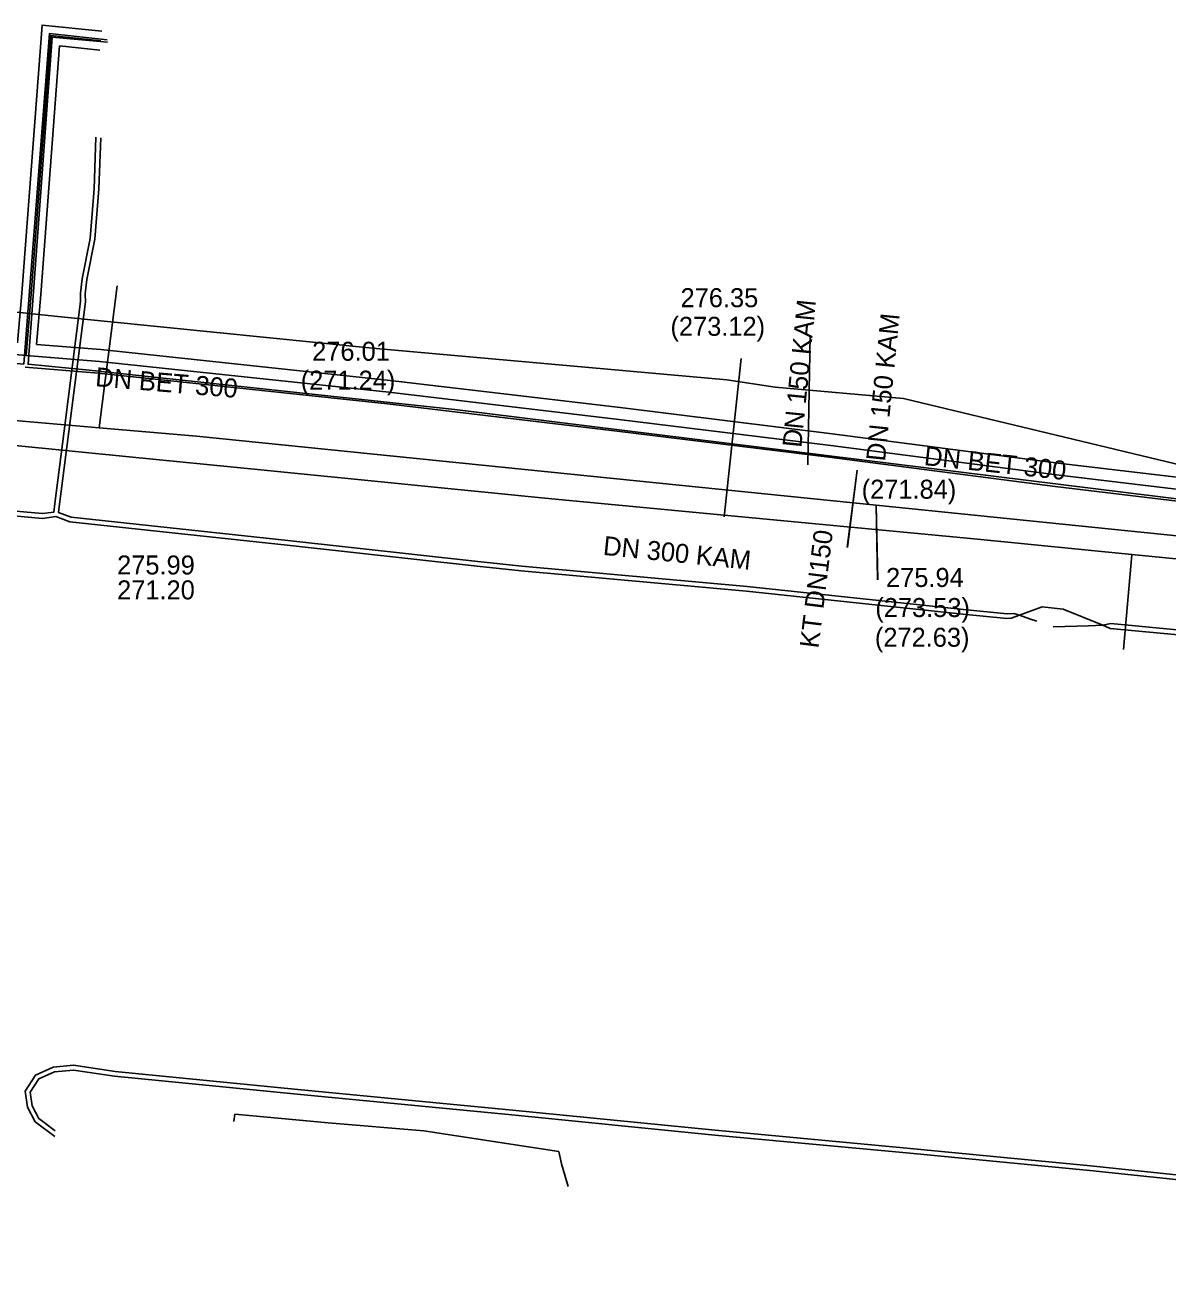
# Model space of a CAD drawing. Extents: x -598233 to -596890, y -1157848 to -1156431.
# Drawn here: x -597803.5 to -597755.4, y -1156911.9 to -1156859.1 of the extents above; entities that cross this region are included whole.
import ezdxf

# ---------------------------------------------------------------- set-up
doc = ezdxf.new("R2010")
doc.units = 0
for name, color, linetype in [('G_TEXTY', 7, 'Continuous'), ('G_ZNACKY', 7, 'Continuous'), ('Vrstva 1', 7, 'Continuous'), ('Vrstva 13', 7, 'Continuous'), ('Vrstva 25', 7, 'Continuous'), ('Vrstva 26', 7, 'Continuous'), ('Vrstva 4', 7, 'Continuous'), ('Vrstva 42', 7, 'Continuous'), ('Vrstva 5', 7, 'Continuous'), ('Vrstva 55', 7, 'Continuous'), ('Vrstva 8', 7, 'Continuous')]:
    doc.layers.add(name, color=color, linetype=linetype)

msp = doc.modelspace()

# ---------------------------------------------------------------- linework, layer by layer
at = {"layer": 'G_ZNACKY'}
for p, q in [((-597770.46, -1156872.16), (-597770.563, -1156877.625)), ((-597768.89, -1156881.1), (-597768.484, -1156877.847))]:
    msp.add_line(p, q, dxfattribs=at)
at = {"layer": 'Vrstva 1'}
msp.add_lwpolyline([(-597768.484, -1156877.847), (-597768.902, -1156881.085)], dxfattribs=at)
at = {"layer": 'Vrstva 13'}
for points in [[(-597774.086, -1156879.82), (-597773.369, -1156873.148)], [(-597707.141, -1156886.777), (-597707.21, -1156886.88), (-597708.44, -1156887.36), (-597721.95, -1156885.49), (-597723.186, -1156885.318), (-597727.88, -1156884.67), (-597739.67, -1156883.1), (-597745.58, -1156882.52), (-597745.891, -1156882.484), (-597756.92, -1156881.402), (-597763.41, -1156880.76), (-597774.077, -1156879.748), (-597781.64, -1156879.03), (-597793.73, -1156877.82), (-597799.14, -1156877.29), (-597828.811, -1156874.332)], [(-597756.92, -1156881.412), (-597757.262, -1156885.406)]]:
    msp.add_lwpolyline(points, dxfattribs=at)
at = {"layer": 'Vrstva 25'}
for points in [[(-597803.481, -1156873.014), (-597803.265, -1156870.42), (-597802.443, -1156859.544), (-597800.33, -1156859.76)], [(-597825.873, -1156870.885), (-597812.889, -1156872.154), (-597803.481, -1156873.014)], [(-597803.481, -1156873.014), (-597800.385, -1156873.271), (-597788.212, -1156874.565), (-597778.522, -1156875.708), (-597769.593, -1156876.811), (-597760.081, -1156878.043), (-597750.933, -1156879.134), (-597751.629, -1156885.489), (-597748.81, -1156885.81), (-597748.974, -1156887.872)]]:
    msp.add_lwpolyline(points, dxfattribs=at)
at = {"layer": 'Vrstva 26'}
for points in [[(-597800.289, -1156859.362), (-597802.811, -1156859.104), (-597803.664, -1156870.388), (-597803.837, -1156872.479)], [(-597800.371, -1156860.158), (-597802.075, -1156859.983), (-597802.866, -1156870.452), (-597803.04, -1156872.549)], [(-597803.04, -1156872.549), (-597800.338, -1156872.773), (-597788.156, -1156874.068), (-597778.462, -1156875.211), (-597769.531, -1156876.315), (-597760.02, -1156877.547), (-597750.382, -1156878.697), (-597751.077, -1156885.048), (-597748.274, -1156885.367), (-597748.476, -1156887.911)], [(-597749.44, -1156887.419), (-597749.347, -1156886.252), (-597752.18, -1156885.929), (-597751.484, -1156879.572), (-597760.143, -1156878.54), (-597769.656, -1156877.307), (-597778.582, -1156876.204), (-597788.268, -1156875.061), (-597800.432, -1156873.768), (-597803.522, -1156873.512)]]:
    msp.add_lwpolyline(points, dxfattribs=at)
at = {"layer": 'Vrstva 42'}
for points in [[(-597848.22, -1156876.73), (-597848.22, -1156876.62), (-597847.49, -1156869.07), (-597825.81, -1156871.24), (-597815.01, -1156872.35), (-597803.58, -1156873.38), (-597802.5, -1156859.46), (-597800.07, -1156859.73)], [(-597800.05, -1156859.82), (-597802.39, -1156859.61), (-597803.4, -1156873.39), (-597800.82, -1156873.63), (-597785.43, -1156875.29), (-597751.39, -1156879.5), (-597752.05, -1156885.8), (-597749.2, -1156886.17), (-597749.33, -1156887.53), (-597753.06, -1156887.15)], [(-597800.54, -1156863.83), (-597800.62, -1156865.994), (-597800.789, -1156868.096), (-597801.119, -1156869.785), (-597801.189, -1156870.399), (-597801.185, -1156870.745), (-597801.879, -1156876.187), (-597802.269, -1156879.258), (-597802.31, -1156879.612), (-597802.792, -1156879.679), (-597805.2, -1156879.46), (-597813.26, -1156878.621), (-597821.628, -1156877.739), (-597822.181, -1156877.892)], [(-597760.91, -1156884.21), (-597761.228, -1156884.103), (-597761.651, -1156883.958), (-597761.887, -1156883.878), (-597762.169, -1156883.9), (-597764.01, -1156883.711), (-597773.12, -1156882.741), (-597782.61, -1156881.89), (-597784.459, -1156881.691), (-597792.459, -1156880.811), (-597801.587, -1156879.822), (-597802.112, -1156879.633), (-597802.071, -1156879.282), (-597801.681, -1156876.213), (-597800.985, -1156870.754), (-597800.991, -1156870.421), (-597800.921, -1156869.815), (-597800.591, -1156868.124), (-597800.42, -1156866.006), (-597800.34, -1156863.85)], [(-597805.22, -1156879.66), (-597802.788, -1156879.881), (-597802.231, -1156879.802), (-597801.633, -1156880.018), (-597792.481, -1156881.009), (-597784.481, -1156881.889), (-597782.63, -1156882.09), (-597773.14, -1156882.939), (-597764.03, -1156883.909), (-597762.171, -1156884.1), (-597761.996, -1156884.087), (-597761.651, -1156883.958), (-597760.69, -1156883.6), (-597759.8, -1156883.7), (-597758.141, -1156884.38), (-597757.823, -1156884.51), (-597751.359, -1156885.12)], [(-597751.341, -1156884.92), (-597757.793, -1156884.312), (-597758.14, -1156884.38), (-597758.141, -1156884.38), (-597758.743, -1156884.397), (-597760.23, -1156884.44)], [(-597751.31, -1156907.911), (-597758.66, -1156907.14), (-597766.391, -1156906.4), (-597774.46, -1156905.65), (-597783, -1156904.8), (-597792.04, -1156903.93), (-597799.728, -1156903.171), (-597801.487, -1156902.909), (-597802.335, -1156902.992), (-597803.088, -1156903.321), (-597803.514, -1156903.997), (-597803.427, -1156904.681), (-597803.098, -1156905.287), (-597802.277, -1156905.905)], [(-597738.863, -1156911.949), (-597738.621, -1156911.71), (-597738.431, -1156911.315), (-597738.34, -1156910.002), (-597738.31, -1156909.598), (-597738.772, -1156909.438), (-597745.33, -1156908.719), (-597751.33, -1156908.109), (-597758.68, -1156907.34), (-597766.409, -1156906.6), (-597774.48, -1156905.85), (-597783.02, -1156905), (-597792.06, -1156904.13), (-597799.752, -1156903.369), (-597801.492, -1156903.111), (-597802.285, -1156903.188), (-597802.952, -1156903.479), (-597803.306, -1156904.043), (-597803.233, -1156904.619), (-597802.942, -1156905.153), (-597802.256, -1156905.675)]]:
    msp.add_lwpolyline(points, dxfattribs=at)
at = {"layer": 'Vrstva 5'}
for p, q in [((-597799.65, -1156870.08), (-597800.401, -1156876.061)), ((-597799.65, -1156870.08), (-597800.401, -1156876.061)), ((-597767.685, -1156879.322), (-597767.611, -1156882.463)), ((-597767.62, -1156882.46), (-597767.685, -1156879.322))]:
    msp.add_line(p, q, dxfattribs=at)
for points in [[(-597796.306, -1156876.415), (-597800.401, -1156876.061), (-597812.037, -1156875.055), (-597826.675, -1156873.789)], [(-597749.926, -1156881.126), (-597767.685, -1156879.322), (-597796.306, -1156876.415)]]:
    msp.add_lwpolyline(points, dxfattribs=at)
at = {"layer": 'Vrstva 55'}
for p, q in [((-597794.73, -1156905.28), (-597794.69, -1156904.97)), ((-597794.69, -1156904.97), (-597790.76, -1156905.33)), ((-597790.76, -1156905.33), (-597786.73, -1156905.67)), ((-597786.73, -1156905.67), (-597781.05, -1156906.54)), ((-597781.05, -1156906.54), (-597780.94, -1156907.06)), ((-597780.94, -1156907.06), (-597780.65, -1156908.01))]:
    msp.add_line(p, q, dxfattribs=at)
msp.add_lwpolyline([(-597742.53, -1156884.87), (-597744.27, -1156884.64), (-597744.46, -1156887.07), (-597744.76, -1156887.6), (-597744.859, -1156887.039), (-597744.669, -1156884.605), (-597748.49, -1156884.27), (-597748.93, -1156883.98), (-597749.03, -1156883.49), (-597748.28, -1156878.34), (-597748.53, -1156878.72), (-597748.88, -1156878.01), (-597750.63, -1156877.77), (-597752.65, -1156877.78), (-597754.37, -1156877.75), (-597766.53, -1156874.83), (-597771.94, -1156874.35), (-597773.97, -1156874.05), (-597788.9, -1156872.71), (-597802.28, -1156871.36), (-597805.33, -1156871.04)], dxfattribs=at)

# ---------------------------------------------------------------- texts
at = {"layer": 'G_TEXTY'}
for s, p in [('276.35 ', (-597775.919, -1156870.984)), ('(273.12)', (-597776.344, -1156872.19)), ('(271.84)', (-597768.292, -1156879.05)), ('275.94 ', (-597767.265, -1156882.766)), ('(273.53)', (-597767.716, -1156884.033)), ('(272.63)', (-597767.735, -1156885.285))]:
    msp.add_text(s, height=0.8, dxfattribs=at).set_placement(p)
msp.add_text('KT DN150', height=0.8, rotation=82.892, dxfattribs=at).set_placement((-597770.114, -1156885.373))
at = {"layer": 'Vrstva 4'}
for s, rotation, p in [('DN 150 KAM', 84.287, (-597770.833, -1156876.919)), ('DN 150 KAM', 84.287, (-597767.309, -1156877.497)), ('DN BET 300', 355.2292, (-597800.589, -1156874.309)), ('DN BET 300', 353.9193, (-597765.691, -1156877.631))]:
    msp.add_text(s, height=0.8, rotation=rotation, dxfattribs=at).set_placement(p)
for s, p in [('276.01 ', (-597791.434, -1156873.24)), ('(271.24)', (-597791.916, -1156874.458))]:
    msp.add_text(s, height=0.8, dxfattribs=at).set_placement(p)
at = {"layer": 'Vrstva 8'}
msp.add_text('DN 300 KAM', height=0.8, rotation=354.2003, dxfattribs=at).set_placement((-597779.207, -1156881.414))
for s, p in [('275.99', (-597799.648, -1156882.24)), ('271.20', (-597799.648, -1156883.29))]:
    msp.add_text(s, height=0.8, dxfattribs=at).set_placement(p)

doc.saveas('drawing.dxf')
